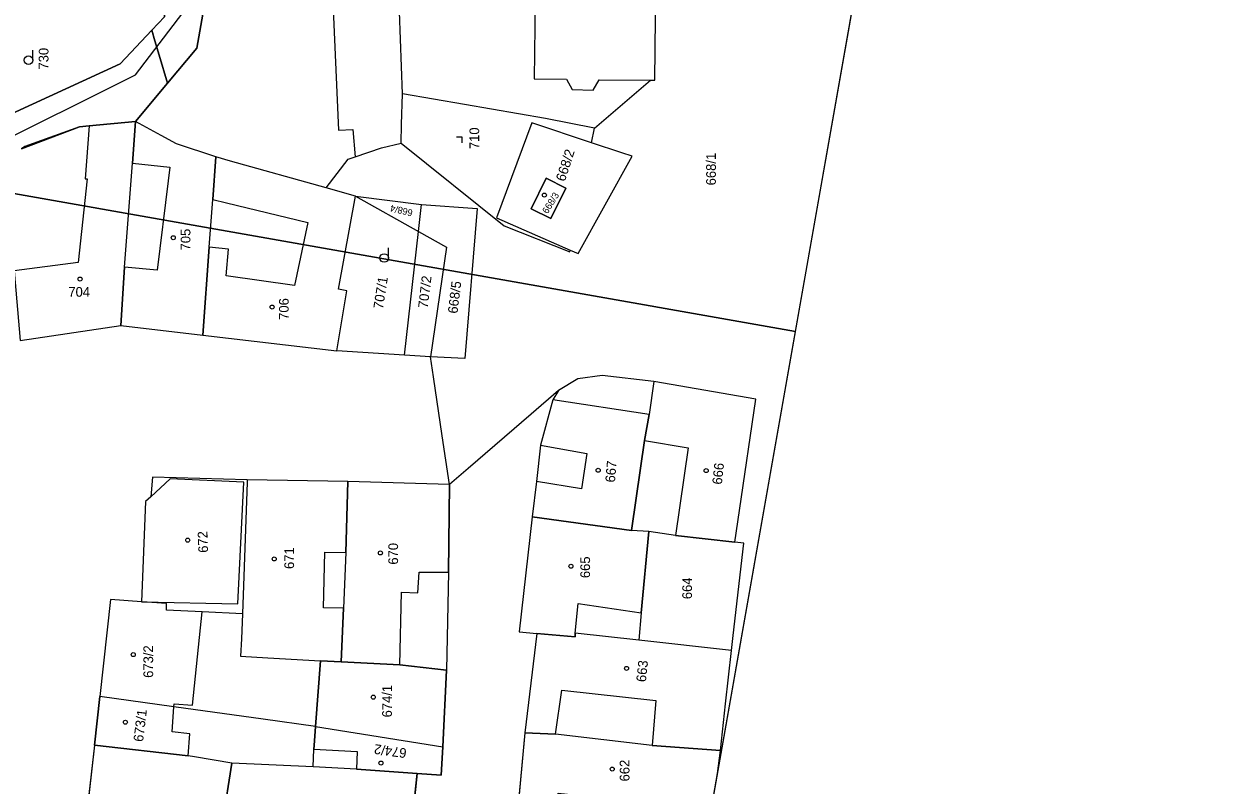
# Model space of a CAD drawing. Extents: x -534481 to -534262, y -1190577 to -1190138.
# Drawn here: x -534365.7 to -534261.7, y -1190410 to -1190343.4 of the extents above; entities that cross this region are included whole.
import ezdxf

# ---------------------------------------------------------------- set-up
doc = ezdxf.new("R2010")
doc.units = 0
for name, color, linetype in [('_KN_Město_Hluk', 7, 'Continuous'), ('_KN_Povodí_Moravy', 7, 'Continuous'), ('_N_osa', 7, 'Continuous'), ('_rámeček', 7, 'Continuous'), ('_rámeček_mřížka', 7, 'Continuous'), ('Hranice parcel', 7, 'Continuous'), ('Parcelní čísla', 7, 'Continuous'), ('Polygon budovy', 7, 'Continuous'), ('Značky budov', 7, 'Continuous'), ('Značky kultur', 7, 'Continuous')]:
    doc.layers.add(name, color=color, linetype=linetype)

msp = doc.modelspace()

# ---------------------------------------------------------------- linework, layer by layer
at = {"layer": '_KN_Město_Hluk'}
for p, q in [((-534353.09, -1190348.56), (-534353.82, -1190346.09)), ((-534355.88, -1190351.91), (-534353.09, -1190348.56)), ((-534359.93, -1190352.28), (-534355.88, -1190351.91))]:
    msp.add_line(p, q, dxfattribs=at)
for points in [[(-534354.46, -1190343.91), (-534357.22, -1190346.86), (-534374.45, -1190354.76)], [(-534353.82, -1190346.09), (-534354.18, -1190344.85), (-534354.46, -1190343.91)], [(-534365.87, -1190354.29), (-534360.78, -1190352.36), (-534359.93, -1190352.28)]]:
    msp.add_lwpolyline(points, dxfattribs=at)
at = {"layer": '_KN_Povodí_Moravy'}
for points in [[(-534353.4, -1190337.34), (-534353.36, -1190342.74), (-534354.46, -1190343.91)], [(-534353.09, -1190348.56), (-534350.53, -1190345.48), (-534349.9, -1190342.02), (-534349.69, -1190337.24)], [(-534354.46, -1190343.91), (-534354.18, -1190344.85), (-534353.82, -1190346.09), (-534353.09, -1190348.56)]]:
    msp.add_lwpolyline(points, dxfattribs=at)
at = {"layer": '_N_osa'}
msp.add_lwpolyline([(-534409.87, -1190391.44), (-534405.95, -1190382.82), (-534400.87, -1190377.49), (-534393.7, -1190372.72), (-534384.93, -1190365.48), (-534382.63, -1190361.15), (-534355.89, -1190347.82), (-534351.74, -1190342.39), (-534351.58, -1190328.32), (-534347.2, -1190300.92), (-534345.55, -1190283.64), (-534344.68, -1190264.49)], dxfattribs=at)
at = {"layer": '_rámeček'}
for p, q in [((-534298.13, -1190370.27), (-534279.9, -1190266.87)), ((-534316.37, -1190473.68), (-534298.13, -1190370.27))]:
    msp.add_line(p, q, dxfattribs=at)
for points in [[(-534407.91, -1190137.67), (-534480.84, -1190551.29), (-534334.6, -1190577.08), (-534261.67, -1190163.46)], [(-534328.65, -1190258.27), (-534426.15, -1190241.08), (-534444.38, -1190344.48), (-534298.13, -1190370.27)], [(-534298.13, -1190370.27), (-534444.38, -1190344.48), (-534462.61, -1190447.89), (-534316.37, -1190473.68)]]:
    msp.add_lwpolyline(points, dxfattribs=at)
at = {"layer": '_rámeček_mřížka'}
msp.add_line((-534301.09, -1190369.75), (-534298.13, -1190370.27), dxfattribs=at)
msp.add_lwpolyline([(-534480.84, -1190551.29), (-534334.6, -1190577.08), (-534261.67, -1190163.46)], dxfattribs=at)
at = {"layer": 'Hranice parcel'}
for p, q in [((-534353.09, -1190348.56), (-534355.88, -1190351.91)), ((-534315.98, -1190353.76), (-534315.73, -1190352.48)), ((-534336.63, -1190358.42), (-534339.19, -1190357.71)), ((-534336.63, -1190358.42), (-534330.85, -1190359.15)), ((-534336.63, -1190358.42), (-534331.12, -1190361.52)), ((-534331.12, -1190361.52), (-534330.85, -1190359.15)), ((-534332.34, -1190372.35), (-534331.12, -1190361.52)), ((-534365.97, -1190371.05), (-534357.17, -1190369.75)), ((-534357.17, -1190369.75), (-534349.98, -1190370.59)), ((-534349.98, -1190370.59), (-534338.27, -1190371.97)), ((-534332.34, -1190372.35), (-534338.27, -1190371.97)), ((-534330.07, -1190372.49), (-534332.34, -1190372.35)), ((-534310.54, -1190374.65), (-534315.06, -1190374.11)), ((-534310.54, -1190374.65), (-534310.94, -1190377.52)), ((-534301.59, -1190376.19), (-534310.54, -1190374.65)), ((-534337.31, -1190383.4), (-534346.1, -1190383.23)), ((-534328.4, -1190383.66), (-534337.31, -1190383.4)), ((-534312.48, -1190387.67), (-534321.18, -1190386.48)), ((-534310.97, -1190387.76), (-534312.48, -1190387.67)), ((-534310.97, -1190387.76), (-534311.63, -1190394.88)), ((-534358.08, -1190393.72), (-534359.01, -1190402.18)), ((-534355.36, -1190393.91), (-534358.08, -1190393.72)), ((-534311.63, -1190394.88), (-534311.85, -1190397.27)), ((-534320.78, -1190396.67), (-534321.81, -1190405.38)), ((-534303.73, -1190398.17), (-534311.85, -1190397.27)), ((-534340.13, -1190404.83), (-534339.69, -1190399.07)), ((-534339.69, -1190399.07), (-534337.9, -1190399.17)), ((-534328.66, -1190399.89), (-534329, -1190406.6)), ((-534359.48, -1190406.45), (-534359.01, -1190402.18)), ((-534340.26, -1190406.48), (-534340.13, -1190404.83)), ((-534340.13, -1190404.83), (-534329, -1190406.6)), ((-534321.81, -1190405.38), (-534322.86, -1190416.77)), ((-534359.48, -1190406.45), (-534361.32, -1190422.75)), ((-534340.34, -1190408.33), (-534347.45, -1190408.02)), ((-534331.23, -1190408.93), (-534332.91, -1190424.36))]:
    msp.add_line(p, q, dxfattribs=at)
for points in [[(-534354.46, -1190343.91), (-534353.36, -1190342.74), (-534353.4, -1190337.34)], [(-534349.69, -1190337.24), (-534349.69, -1190337.44), (-534349.9, -1190342.02), (-534350.53, -1190345.48), (-534353.09, -1190348.56)], [(-534332.53, -1190349.48), (-534332.78, -1190342.31), (-534332.83, -1190337.12)], [(-534315.73, -1190352.48), (-534310.81, -1190348.3), (-534310.45, -1190348.3), (-534310.32, -1190337.38), (-534310.32, -1190337.25)], [(-534374.45, -1190354.76), (-534357.22, -1190346.86), (-534354.46, -1190343.91)], [(-534354.46, -1190343.91), (-534354.18, -1190344.85), (-534353.82, -1190346.09), (-534353.09, -1190348.56)], [(-534332.65, -1190353.81), (-534332.6, -1190352.16), (-534332.53, -1190349.48)], [(-534315.73, -1190352.48), (-534320, -1190351.64), (-534327.1, -1190350.42), (-534332.53, -1190349.48)], [(-534355.88, -1190351.91), (-534359.93, -1190352.28), (-534360.78, -1190352.36), (-534365.58, -1190354.08), (-534365.87, -1190354.29)], [(-534357.17, -1190369.75), (-534356.84, -1190364.64), (-534356.15, -1190355.55), (-534355.88, -1190351.91)], [(-534348.86, -1190355), (-534352.29, -1190353.85), (-534353.64, -1190353.12), (-534355.88, -1190351.91)], [(-534315.98, -1190353.76), (-534321.21, -1190352.03), (-534324.29, -1190360.33), (-534317.85, -1190363.15)], [(-534339.19, -1190357.71), (-534337.29, -1190355.2), (-534336.67, -1190354.99), (-534334.35, -1190354.21), (-534332.65, -1190353.81)], [(-534332.65, -1190353.81), (-534323.62, -1190361.03), (-534317.88, -1190363.31), (-534317.85, -1190363.15)], [(-534317.85, -1190363.15), (-534317.16, -1190363.45), (-534312.43, -1190354.94), (-534313.32, -1190354.65), (-534315.98, -1190353.76)], [(-534349.98, -1190370.59), (-534349.44, -1190362.88), (-534349.13, -1190358.72), (-534348.86, -1190355)], [(-534339.19, -1190357.71), (-534347.58, -1190355.36), (-534348.86, -1190355)], [(-534318.22, -1190357.73), (-534319.55, -1190360.4), (-534321.26, -1190359.54), (-534319.94, -1190356.87), (-534318.22, -1190357.73)], [(-534338.27, -1190371.97), (-534337.38, -1190366.71), (-534338.11, -1190366.57), (-534336.63, -1190358.42)], [(-534330.85, -1190359.15), (-534326, -1190359.52), (-534327.08, -1190372.63), (-534330.07, -1190372.49)], [(-534331.12, -1190361.52), (-534328.67, -1190362.89), (-534330.07, -1190372.49)], [(-534328.4, -1190383.66), (-534329.04, -1190379.4), (-534329.81, -1190374.24), (-534330.07, -1190372.49)], [(-534315.06, -1190374.11), (-534317.18, -1190374.42), (-534318.86, -1190375.44)], [(-534318.86, -1190375.44), (-534321.27, -1190377.51), (-534326.78, -1190382.26), (-534328.4, -1190383.66)], [(-534318.86, -1190375.44), (-534319.37, -1190376.25), (-534320.44, -1190380.21), (-534320.81, -1190383.39), (-534321.18, -1190386.48)], [(-534303.44, -1190388.7), (-534303.03, -1190385.92), (-534301.59, -1190376.19)], [(-534310.94, -1190377.52), (-534311.35, -1190379.79), (-534312.08, -1190384.85), (-534312.48, -1190387.67)], [(-534346.1, -1190383.23), (-534354.41, -1190383.01), (-534354.55, -1190384.72), (-534355, -1190385.14), (-534355.36, -1190393.91)], [(-534346.1, -1190383.23), (-534346.11, -1190383.45), (-534346.53, -1190394.95)], [(-534337.31, -1190383.4), (-534337.47, -1190389.59), (-534337.69, -1190394.47), (-534337.9, -1190399.17)], [(-534328.4, -1190383.66), (-534328.51, -1190391.31), (-534328.66, -1190399.89)], [(-534321.18, -1190386.48), (-534322.3, -1190396.55), (-534320.78, -1190396.67)], [(-534303.44, -1190388.7), (-534308.63, -1190388.11), (-534310.97, -1190387.76)], [(-534303.73, -1190398.17), (-534303.58, -1190396.85), (-534302.64, -1190388.78), (-534303.44, -1190388.7)], [(-534346.53, -1190394.95), (-534350.05, -1190394.78), (-534353.16, -1190394.63), (-534353.18, -1190394.06), (-534355.29, -1190393.91), (-534355.36, -1190393.91)], [(-534346.53, -1190394.95), (-534346.62, -1190397.16), (-534346.69, -1190398.67), (-534344.32, -1190398.81), (-534339.69, -1190399.07)], [(-534311.85, -1190397.27), (-534317.4, -1190396.66), (-534317.42, -1190396.96), (-534320.78, -1190396.67)], [(-534304.7, -1190406.9), (-534304.25, -1190402.82), (-534303.73, -1190398.17)], [(-534337.9, -1190399.17), (-534332.75, -1190399.41), (-534328.66, -1190399.89)], [(-534340.13, -1190404.83), (-534344.71, -1190404.18), (-534352.53, -1190403.09), (-534359.01, -1190402.18)], [(-534304.7, -1190406.9), (-534310.69, -1190406.47), (-534319.12, -1190405.49), (-534321.81, -1190405.38)], [(-534347.45, -1190408.02), (-534350.73, -1190407.46), (-534351.28, -1190407.37), (-534359.48, -1190406.45)], [(-534340.34, -1190408.33), (-534340.27, -1190406.79), (-534340.26, -1190406.48)], [(-534329, -1190406.6), (-534329.13, -1190409.08), (-534331.23, -1190408.93)], [(-534304.95, -1190408.92), (-534304.7, -1190406.9)], [(-534347.45, -1190408.02), (-534348.24, -1190413.03), (-534349.11, -1190420.99), (-534349.31, -1190422.85)], [(-534331.23, -1190408.93), (-534336.56, -1190408.56), (-534340.34, -1190408.33)]]:
    msp.add_lwpolyline(points, dxfattribs=at)
at = {"layer": 'Polygon budovy'}
msp.add_line((-534306.7, -1190418.82), (-534304.95, -1190408.92), dxfattribs=at)
for points in [[(-534349.9, -1190342.02), (-534347.72, -1190341.99), (-534347.71, -1190342.39), (-534338.59, -1190342.1), (-534338.12, -1190352.66), (-534336.88, -1190352.6), (-534336.67, -1190354.99), (-534334.35, -1190354.21), (-534332.65, -1190353.81), (-534332.6, -1190352.16), (-534332.53, -1190349.48), (-534332.78, -1190342.31), (-534332.83, -1190337.12), (-534337.65, -1190337.15), (-534347.69, -1190337.23), (-534349.69, -1190337.24), (-534349.69, -1190337.44)], [(-534320.89, -1190337.07), (-534320.88, -1190337.18), (-534325.2, -1190337.17), (-534325.09, -1190341.34), (-534320.9, -1190341.35), (-534320.99, -1190348.17), (-534318.18, -1190348.21), (-534317.67, -1190349.12), (-534315.85, -1190349.15), (-534315.3, -1190348.25), (-534310.81, -1190348.3), (-534310.45, -1190348.3), (-534310.32, -1190337.38)], [(-534366.5, -1190364.95), (-534365.97, -1190371.05), (-534357.17, -1190369.75), (-534356.84, -1190364.64), (-534356.15, -1190355.55), (-534355.88, -1190351.91), (-534359.93, -1190352.28), (-534360.28, -1190356.91), (-534360.12, -1190356.93), (-534360.9, -1190364.23)], [(-534352.29, -1190353.85), (-534353.64, -1190353.12), (-534355.88, -1190351.91), (-534356.15, -1190355.55), (-534352.88, -1190355.89), (-534353.03, -1190357.09), (-534353.98, -1190364.91), (-534356.84, -1190364.64), (-534357.17, -1190369.75), (-534349.98, -1190370.59), (-534349.44, -1190362.88), (-534349.13, -1190358.72), (-534348.86, -1190355)], [(-534349.44, -1190362.88), (-534349.98, -1190370.59), (-534338.27, -1190371.97), (-534337.38, -1190366.71), (-534338.11, -1190366.57), (-534336.63, -1190358.42), (-534339.19, -1190357.71), (-534347.58, -1190355.36), (-534348.86, -1190355), (-534349.13, -1190358.72), (-534347.93, -1190359.01), (-534340.81, -1190360.75), (-534341.96, -1190366.24), (-534347.94, -1190365.39), (-534347.74, -1190363.06)], [(-534321.26, -1190359.54), (-534319.55, -1190360.4), (-534318.22, -1190357.73), (-534319.94, -1190356.87)], [(-534311.35, -1190379.79), (-534307.52, -1190380.43), (-534308.63, -1190388.11), (-534303.44, -1190388.7), (-534303.03, -1190385.92), (-534301.59, -1190376.19), (-534310.54, -1190374.65), (-534310.94, -1190377.52)], [(-534316.87, -1190384.03), (-534320.81, -1190383.39), (-534321.18, -1190386.48), (-534312.48, -1190387.67), (-534312.08, -1190384.85), (-534311.35, -1190379.79), (-534310.94, -1190377.52), (-534319.37, -1190376.25), (-534320.44, -1190380.21), (-534316.39, -1190380.95)], [(-534355.36, -1190393.91), (-534355.29, -1190393.91), (-534346.92, -1190394.09), (-534346.41, -1190383.44), (-534352.85, -1190383.16), (-534354.55, -1190384.72), (-534355, -1190385.14)], [(-534344.32, -1190398.81), (-534339.69, -1190399.07), (-534337.9, -1190399.17), (-534337.69, -1190394.47), (-534339.43, -1190394.43), (-534339.31, -1190389.56), (-534337.47, -1190389.59), (-534337.31, -1190383.4), (-534346.1, -1190383.23), (-534346.11, -1190383.45), (-534346.53, -1190394.95), (-534346.62, -1190397.16), (-534346.69, -1190398.67)], [(-534332.62, -1190393.06), (-534331.17, -1190393.14), (-534331.06, -1190391.32), (-534328.51, -1190391.31), (-534328.4, -1190383.66), (-534337.31, -1190383.4), (-534337.47, -1190389.59), (-534337.69, -1190394.47), (-534337.9, -1190399.17), (-534332.75, -1190399.41)], [(-534322.3, -1190396.55), (-534320.78, -1190396.67), (-534317.42, -1190396.96), (-534317.4, -1190396.66), (-534317.14, -1190394.07), (-534311.63, -1190394.88), (-534310.97, -1190387.76), (-534312.48, -1190387.67), (-534321.18, -1190386.48)], [(-534359.48, -1190406.45), (-534351.28, -1190407.37), (-534351.13, -1190405.45), (-534352.67, -1190405.29), (-534352.53, -1190403.09), (-534352.51, -1190402.82), (-534350.91, -1190402.96), (-534350.29, -1190397.04), (-534350.05, -1190394.78), (-534353.16, -1190394.63), (-534353.18, -1190394.06), (-534355.29, -1190393.91), (-534355.36, -1190393.91), (-534358.08, -1190393.72), (-534359.01, -1190402.18)], [(-534317.4, -1190396.66), (-534317.42, -1190396.96), (-534320.78, -1190396.67), (-534321.81, -1190405.38), (-534319.12, -1190405.49), (-534318.59, -1190401.64), (-534310.36, -1190402.55), (-534310.69, -1190406.47), (-534304.7, -1190406.9), (-534304.25, -1190402.82), (-534303.73, -1190398.17), (-534311.85, -1190397.27)], [(-534329, -1190406.6), (-534328.66, -1190399.89), (-534332.75, -1190399.41), (-534337.9, -1190399.17), (-534339.69, -1190399.07), (-534340.13, -1190404.83), (-534340.26, -1190406.48), (-534340.27, -1190406.79), (-534336.48, -1190406.99), (-534336.56, -1190408.56), (-534331.23, -1190408.93), (-534329.13, -1190409.08)], [(-534350.73, -1190407.46), (-534351.28, -1190407.37), (-534359.48, -1190406.45), (-534361.32, -1190422.75), (-534349.49, -1190424.31), (-534349.31, -1190422.85), (-534349.11, -1190420.99), (-534351.71, -1190420.68), (-534353.09, -1190421.73), (-534356.12, -1190421.36), (-534355.1, -1190412.3), (-534348.24, -1190413.03), (-534347.45, -1190408.02)], [(-534349.31, -1190422.85), (-534346.43, -1190423.17), (-534346.07, -1190420.03), (-534344.47, -1190420.16), (-534344.27, -1190417.73), (-534345.78, -1190417.61), (-534345.25, -1190412.99), (-534338.47, -1190413.36), (-534338.99, -1190419.24), (-534337.36, -1190419.45), (-534337.91, -1190424.11), (-534332.91, -1190424.36), (-534331.23, -1190408.93), (-534336.56, -1190408.56), (-534340.34, -1190408.33), (-534347.45, -1190408.02), (-534348.24, -1190413.03), (-534349.11, -1190420.99)]]:
    msp.add_lwpolyline(points, close=True, dxfattribs=at)
msp.add_lwpolyline([(-534304.95, -1190408.92), (-534304.7, -1190406.9), (-534310.69, -1190406.47), (-534319.12, -1190405.49), (-534321.81, -1190405.38), (-534322.86, -1190416.77), (-534319.66, -1190417.17), (-534318.89, -1190410.64), (-534311.23, -1190411.47), (-534311.53, -1190414.36), (-534313.6, -1190414.13), (-534314.01, -1190417.87), (-534306.7, -1190418.82)], dxfattribs=at)
at = {"layer": 'Značky budov'}
for centre in [(-534320.11, -1190358.34), (-534352.58, -1190362.07), (-534360.74, -1190365.68), (-534343.93, -1190368.13), (-534315.4, -1190382.41), (-534305.95, -1190382.44), (-534351.32, -1190388.52), (-534334.46, -1190389.64), (-534343.75, -1190390.16), (-534317.78, -1190390.8), (-534356.08, -1190398.53), (-534312.92, -1190399.73), (-534335.08, -1190402.25), (-534356.77, -1190404.44), (-534334.41, -1190408.01), (-534314.17, -1190408.54)]:
    msp.add_circle(centre, 0.175, dxfattribs=at)
at = {"layer": 'Značky kultur'}
for p, q in [((-534364.87, -1190346.53), (-534364.87, -1190345.66)), ((-534327.29, -1190353.28), (-534327.79, -1190353.28)), ((-534327.29, -1190353.78), (-534327.29, -1190353.28)), ((-534333.75, -1190363.84), (-534333.75, -1190362.96))]:
    msp.add_line(p, q, dxfattribs=at)
for centre in [(-534365.25, -1190346.53), (-534334.13, -1190363.84)]:
    msp.add_circle(centre, 0.375, dxfattribs=at)

# ---------------------------------------------------------------- texts
at = {"layer": 'Parcelní čísla'}
for s, height, rotation, p in [('730', 0.85, 90, (-534363.5, -1190347.36)), ('710', 0.85, 90, (-534325.81, -1190354.32)), ('668/2', 0.85, 72, (-534318.32, -1190357.21)), ('668/1', 0.85, 90, (-534305.1, -1190357.49)), ('668/3', 0.595, 58, (-534319.84, -1190360.03)), ('668/4', 0.595, 166.3082, (-534331.58, -1190359.64)), ('705', 0.85, 90, (-534351.08, -1190363.18)), ('707/1', 0.85, 81, (-534334.24, -1190368.35)), ('707/2', 0.85, 83, (-534330.32, -1190368.27)), ('668/5', 0.85, 83, (-534327.72, -1190368.74)), ('706', 0.85, 90, (-534342.48, -1190369.25)), ('667', 0.85, 85, (-534313.94, -1190383.5)), ('666', 0.85, 84, (-534304.58, -1190383.69)), ('672', 0.85, 92, (-534349.53, -1190389.61)), ('671', 0.85, 90, (-534342.01, -1190391.04)), ('670', 0.85, 90, (-534332.91, -1190390.66)), ('665', 0.85, 90, (-534316.11, -1190391.84)), ('664', 0.85, 90, (-534307.19, -1190393.68)), ('673/2', 0.85, 90, (-534354.34, -1190400.56)), ('663', 0.85, 84, (-534311.23, -1190400.96)), ('674/1', 0.85, 90, (-534333.45, -1190404.02)), ('673/1', 0.85, 83, (-534355.23, -1190406.19)), ('674/2', 0.85, 172, (-534332.12, -1190406.75)), ('662', 0.85, 90, (-534312.66, -1190409.62))]:
    msp.add_text(s, height=height, rotation=rotation, dxfattribs=at).set_placement(p)
msp.add_text('704', height=0.85, dxfattribs=at).set_placement((-534361.76, -1190367.23))

doc.saveas('drawing.dxf')
